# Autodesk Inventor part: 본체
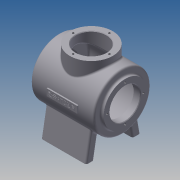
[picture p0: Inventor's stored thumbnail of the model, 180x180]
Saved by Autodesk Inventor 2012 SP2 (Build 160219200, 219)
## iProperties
Created: 2015-01
Part Number: 본체
Material: 알루미늄-6061
Document SubType Name: Modeling
Designer: cad-02
Mass: 1024.69 g
Surface Area: 1060.49 cm^2
Volume: 378.115 cm^3
Density: 2.71 g/cm^3
Author: cad-02
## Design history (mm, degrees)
sketch "스케치1"
  geometry: C1 r 50 at (0, 0); 1 further point
  constraints: 1 centre point, 1 coincident
  dimensions: "d0" = 100 diameter of C1
extrude "돌출1" new body sketch "스케치1" distance "d1" = 112; taper "d2" = 0 deg
sketch "스케치2"
  geometry: C1 r 50 at (0, 0) reference; C2 r 38 at (0, 0)
  constraints: 1 centre point, 1 coincident
  dimensions: "d3" = 76 diameter of C2
extrude "돌출2" join sketch "스케치2" distance "d4" = 5; taper "d5" = 0 deg
sketch "스케치3"
  geometry: C1 r 50 at (0, 0) reference; C2 r 38 at (0, 0)
  constraints: 1 centre point, 1 coincident
  dimensions: "d6" = 76 diameter of C2
extrude "돌출3" join sketch "스케치3" distance "d7" = 5; taper "d8" = 0 deg
node "작업 평면1"
sketch "스케치4"
  geometry: L1 (0, 50)-(112, 50) reference; L2 (0, 50)-(0, -50) reference; L3 (-5, -38)-(-5, 38) reference; C1 r 38 at (57, 0); 2 further points
  constraints: 1 centre point, 1 horizontal alignment, 1 midpoint
  dimensions: "d10" = 76 diameter of C1; "d107" = 62 distance from line of C1.centre L3
extrude "돌출4" join sketch "스케치4" stored distance "d11" = 5; taper "d12" = 0 deg
hole "구멍1" diameter "d15" = 54; stored, may be unused: countersink angle "d19" = 90 deg, drill point angle "d21" = 0 deg; dims "d13" = 10, "d14" = 10, "d16" = 6, "d17" = 4, "d18" = 2, "d20" = 40
hole "구멍2" diameter "d24" = 54; stored, may be unused: countersink angle "d28" = 90 deg, drill point angle "d30" = 0 deg; dims "d22" = 10, "d23" = 10, "d25" = 6, "d26" = 4, "d27" = 2, "d29" = 12
hole "구멍3" diameter "d33" = 90; stored, may be unused: countersink angle "d37" = 90 deg, drill point angle "d39" = 0 deg; dims "d31" = 10, "d32" = 10, "d34" = 6, "d35" = 4, "d36" = 2, "d38" = 97
hole "구멍4" diameter "d42" = 54; stored, may be unused: countersink angle "d46" = 90 deg, drill point angle "d48" = 0 deg; dims "d43" = 6, "d44" = 4, "d45" = 2, "d47" = 13, "d49" = 10, "d50" = 10
node "작업 평면3"
sketch "스케치8"
  geometry: L1 (30.865, -39.336)-(80, -48); L2 (80, -48)-(80, -34); L3 (80, -34)-(41.901, -27.282); L4 (80, 34)-(80, 48); L5 (80, 48)-(30.865, 39.336); L6 (41.901, 27.282)-(80, 34); C1 r 45 at (0, 0) reference; A1 r 50 centre (0, 0) between (30.865, -39.336) and (41.901, -27.282) reference; 1 further point
  constraints: 12 end point, 4 point on circle, 2 equal length, 1 collinear, 1 parallel, 1 vertical
  dimensions: "d51" = 96 distance of L4.end L1.end; "d52" = 80 deg angle of L6 L4; "d53" = 100 deg angle of L4 L5; "d54" = 100 deg angle of L2 L1; "d55" = 80 distance from line of point (0, 0) L2; "d108" = 14 distance of L2.end L1.end
extrude "돌출5" join sketch "스케치8" stored distance "d57" = 80; taper "d58" = 0 deg
sketch "스케치10"
  geometry: C1 r 27 at (0, 0) reference; 1 further point
  constraints: 1 horizontal alignment
  dimensions: "d59" = 32 distance of C1.centre point (-32, 0)
hole "구멍5" sketch "스케치10" at (-32, 0) diameter "d60" = 3.242; stored, may be unused: countersink angle "d64" = 90 deg, drill point angle "d66" = 118 deg; dims "d61" = 8, "d62" = 4, "d63" = 2, "d65" = 10
sketch "스케치11"
  geometry: C1 r 27 at (0, 0) reference; 1 further point
  constraints: 1 horizontal alignment
  dimensions: "d70" = 32 distance of point (32, 0) C1.centre
hole "구멍6" sketch "스케치11" at (32, 0) diameter "d71" = 3.242; stored, may be unused: countersink angle "d75" = 90 deg, drill point angle "d77" = 118 deg; dims "d72" = 8, "d73" = 4, "d74" = 2, "d76" = 10
sketch "스케치12"
  geometry: C1 r 27 at (0, 0) reference; 2 further points
  constraints: 1 horizontal alignment
  dimensions: "d81" = 32 distance of C1.centre point (32, 0)
hole "구멍7" sketch "스케치12" at (32, 0) diameter "d82" = 3.242; stored, may be unused: countersink angle "d86" = 90 deg, drill point angle "d88" = 118 deg; dims "d83" = 8, "d84" = 4, "d85" = 2, "d87" = 10
node "작업 평면4"
sketch "스케치15"
  geometry: L1 (30, 6)-(30, -6); L2 (30, -6)-(84, -6); L3 (84, -6)-(84, 6); L4 (84, 6)-(30, 6); L5 (-5, -38)-(-5, 38) reference; L6 (57, 6)-(57, -6); 2 further points
  constraints: 10 end point, 3 midpoint, 2 parallel, 1 horizontal alignment, 1 perpendicular, 1 vertical
  dimensions: "d93" = 12 distance between parallel lines of L4 L2; "d94" = 54 distance between parallel lines of L3 L1; "d95" = 62 distance between parallel lines of L6 L5
extrude "돌출6" join sketch "스케치15" stored distance "d96" = 80; taper "d97" = 0 deg
sketch "스케치16"
  geometry: L1 (30, 6)-(30, -6) reference; L2 (84, 6)-(30, 6) reference; 4 further points
  constraints: 2 midpoint, 1 horizontal alignment, 1 vertical alignment, 1 other
feature "엠보싱1" sketch "스케치16" dims "d98" = 0.5, "d99" = 0
fillet "모깎기1" dims "d100" = 3
fillet "모깎기2" dims "d101" = 3
fillet "모깎기3" dims "d102" = 3
chamfer "모따기1" distance "d103" = 1; stored, may be unused: second distance "d104" = 2, angle "d105" = 45 deg
fillet "모깎기4" dims "d106" = 3
sketch "스케치21"
  geometry: 1 further point
sketch "스케치22"
  geometry: 1 further point
sketch "스케치23"
  geometry: 1 further point
node "솔리드1"
pattern_circular "원형 패턴1" dims angle "d68" = 360 deg
pattern_circular "원형 패턴2" dims angle "d79" = 360 deg
pattern_circular "원형 패턴3" dims angle "d90" = 360 deg
other parameters: "d9" = 62, "d92" = -52
